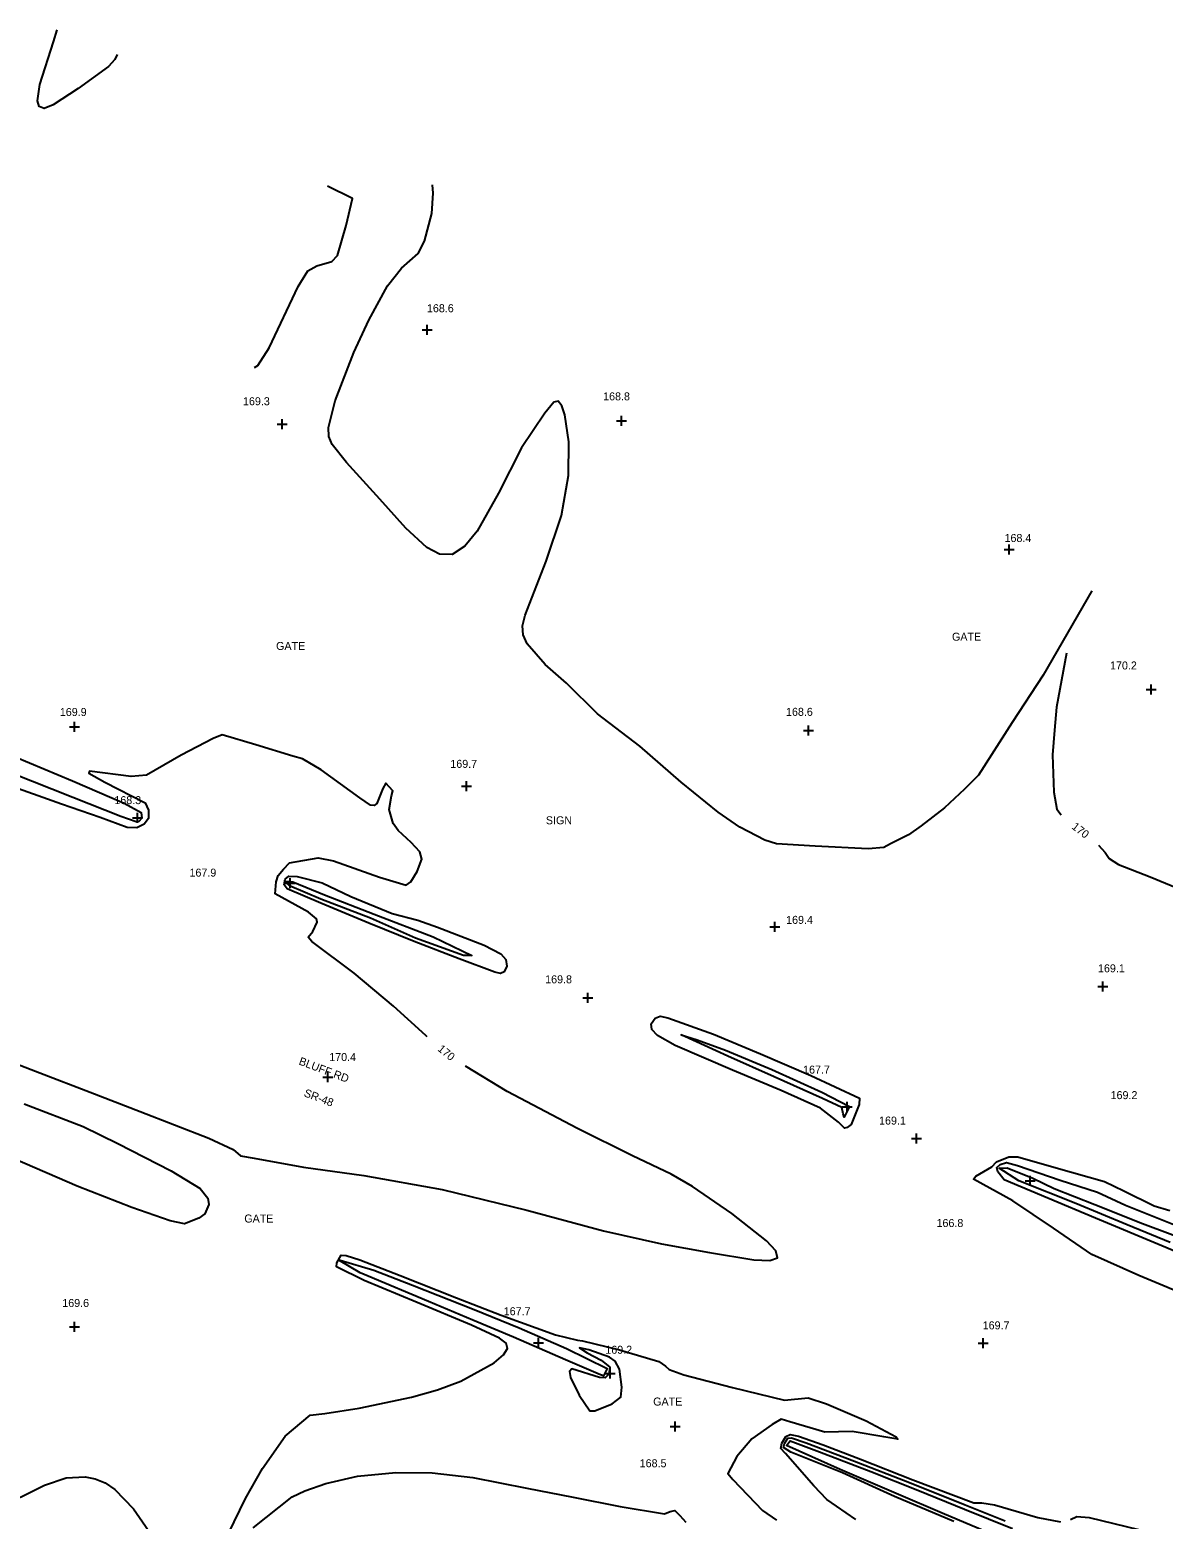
# Model space of a CAD drawing. Extents: x 1475150 to 2003689, y 770235 to 1112803.
# Drawn here: x 1997963.8 to 1998247, y 775726.9 to 776099.2 of the extents above; entities that cross this region are included whole.
import ezdxf

# ---------------------------------------------------------------- set-up
doc = ezdxf.new("R2010")
doc.units = 0
for name, color, linetype in [('RD_DTM_Major1', 7, 'Continuous'), ('RD_DTM_Major1_Lbl', 7, 'Continuous'), ('RD_DTM_Minor1', 7, 'Continuous'), ('RD_DTM_Spot_Elev', 7, 'Continuous'), ('RD_TX_Misc1', 7, 'Continuous')]:
    doc.layers.add(name, color=color, linetype=linetype)

msp = doc.modelspace()

# ---------------------------------------------------------------- linework, layer by layer
at = {"layer": 'RD_DTM_Major1'}
for points in [[(1998019.96, 776014.76), (1998020.76, 776015.27), (1998023.63, 776019.73), (1998030.91, 776035.03), (1998033.26, 776038.93), (1998035.54, 776040.16), (1998039.32, 776041.24), (1998040.67, 776042.8), (1998042.84, 776050.28), (1998044.45, 776057.02), (1998038.17, 776060.1)], [(1998222.83, 775943.4), (1998220.32, 775929.85), (1998219.81, 775924.17), (1998219.34, 775917.98), (1998219.66, 775908.62), (1998220.4, 775904.42), (1998221.54, 775902.99)], [(1998063.14, 775847.46), (1998062.74, 775847.79), (1998054.7, 775855.1), (1998044.9, 775863.38), (1998034.29, 775871.33), (1998033.4, 775872.39), (1998034.52, 775873.83), (1998035.66, 775876.11), (1998035.43, 775876.98), (1998033.43, 775878.65), (1998025.12, 775883.25), (1998025.35, 775886.22), (1998025.85, 775887.77), (1998027.24, 775889.41), (1998028.67, 775890.99), (1998035.87, 775892.18), (1998039.7, 775891.44), (1998051.19, 775887.36), (1998057.85, 775885.35), (1998059.05, 775886.23), (1998060.63, 775888.83), (1998061.75, 775891.91), (1998061.31, 775893.71), (1998059.09, 775896.03), (1998055.87, 775899.08), (1998054.6, 775900.79), (1998053.64, 775904.28), (1998054.23, 775907.75), (1998054.53, 775908.99), (1998052.8, 775910.9), (1998052.02, 775909.54), (1998050.55, 775905.8), (1998049.85, 775905.3), (1998048.97, 775905.4), (1998046.29, 775907.23), (1998036.62, 775914.25), (1998031.93, 775916.97), (1998029.53, 775917.6), (1998020.26, 775920.48), (1998011.87, 775923), (1998009.6, 775922.06), (1998001.63, 775917.86), (1997992.98, 775912.89), (1997989.11, 775912.55), (1997978.73, 775913.89), (1997978.56, 775913.42), (1997982.53, 775911.15), (1997992.66, 775905.98), (1997993.5, 775904.09), (1997993.44, 775902.08), (1997992.4, 775900.62), (1997990.58, 775899.73), (1997988.13, 775899.81), (1997981.41, 775902.27), (1997971.78, 775905.64), (1997957.46, 775910.7)], [(1998230.85, 775895.41), (1998232.49, 775893.59), (1998233.49, 775892.09), (1998235.87, 775890.53), (1998243.76, 775887.44), (1998256.67, 775882.1), (1998274.92, 775874.43), (1998292.72, 775867.08), (1998293.86, 775866.91), (1998296.21, 775871.31)], [(1997955.67, 775842.58), (1997966.34, 775838.47), (1997978.93, 775833.62), (1997991.42, 775828.79), (1998008.55, 775822.13), (1998014.65, 775819.34), (1998016.45, 775817.72), (1998019.84, 775817.12), (1998032.24, 775814.9), (1998047.24, 775812.8), (1998066.85, 775809.3), (1998088, 775804.11), (1998107.12, 775799.01), (1998121.68, 775795.73), (1998133.67, 775793.53), (1998144.73, 775791.74), (1998148.69, 775791.55), (1998150.65, 775792.25), (1998150.18, 775794.02), (1998147.91, 775796.49), (1998139.2, 775803.34), (1998129.4, 775810.1), (1998124.03, 775813.16), (1998114.42, 775817.75), (1998100.7, 775824.58), (1998083.13, 775833.84), (1998072.68, 775840.16)]]:
    msp.add_lwpolyline(points, dxfattribs=at)
at = {"layer": 'RD_DTM_Minor1'}
for points in [[(1997985.62, 776093.01), (1997985.05, 776091.81), (1997983.5, 776090.03), (1997975.89, 776084.54), (1997969.69, 776080.42), (1997967.42, 776079.55), (1997966.17, 776080.01), (1997965.76, 776081.48), (1997966.37, 776085.54), (1997969.75, 776096.22), (1997970.66, 776099.2)], [(1998229.15, 775958.98), (1998217, 775937.88), (1998209.3, 775926.06), (1998200.84, 775912.88), (1998197.36, 775909.38), (1998192.32, 775904.71), (1998186.53, 775900.23), (1998183.35, 775897.98), (1998178.9, 775895.69), (1998177.16, 775894.82), (1998173.31, 775894.44), (1998160.04, 775895.15), (1998150.4, 775895.7), (1998147.44, 775896.6), (1998141.22, 775899.91), (1998135.8, 775903.67), (1998126.54, 775911.16), (1998116.25, 775920.13), (1998105.65, 775928.21), (1998097.93, 775935.87), (1998092.59, 775940.56), (1998088.11, 775945.74), (1998087.08, 775947.98), (1998086.93, 775950.24), (1998087.56, 775952.91), (1998092.85, 775966.37), (1998096.67, 775977.76), (1998098.44, 775987.76), (1998098.46, 775996.17), (1998097.5, 776002.99), (1998096.74, 776005.24), (1998095.81, 776006.34), (1998094.76, 776006.13), (1998092.54, 776003.37), (1998086.71, 775994.69), (1998080.92, 775983.33), (1998075.56, 775973.85), (1998072.55, 775970.14), (1998069.39, 775968.07), (1998066.16, 775968.13), (1998063.03, 775969.76), (1998057.81, 775974.61), (1998051.3, 775981.87), (1998042.95, 775991.07), (1998039.37, 775995.57), (1998038.57, 775997.53), (1998038.45, 775999.76), (1998040.15, 776006.43), (1998044.8, 776018.5), (1998048.51, 776026.62), (1998053.2, 776035.17), (1998056.72, 776039.61), (1998060.88, 776043.29), (1998062.44, 776046.36), (1998064.26, 776053.26), (1998064.6, 776058.36), (1998064.43, 776060.42)], [(1997960.19, 775917.47), (1997974.45, 775911.48), (1997987.39, 775905.86), (1997991.67, 775903.54), (1997991.85, 775902.16), (1997991.08, 775901.34), (1997990.38, 775901.18), (1997986.53, 775902.52), (1997974.57, 775907.33), (1997959.29, 775913.38), (1997946.8, 775918.47), (1997934.61, 775924.25), (1997922.47, 775930.31), (1997917.27, 775932.19), (1997907.92, 775935.34), (1997901.2, 775938.84), (1997901.83, 775938.87), (1997908.61, 775936.91), (1997920.8, 775932.65), (1997932.19, 775928.38), (1997945.99, 775923.09), (1997960.19, 775917.47)], [(1998028.09, 775884.43), (1998027.34, 775885.43), (1998027.59, 775886.87), (1998028.51, 775887.66), (1998030.6, 775887.53), (1998036.91, 775885.98), (1998043.99, 775882.58), (1998054.39, 775878.34), (1998060.74, 775876.65), (1998065.71, 775874.92), (1998077.36, 775870.36), (1998081.51, 775868.22), (1998082.77, 775866.83), (1998083.01, 775865.17), (1998082.35, 775863.73), (1998081.44, 775863.31), (1998080.02, 775863.65), (1998071.11, 775867.01), (1998059.83, 775871.3), (1998048.5, 775875.89), (1998036.52, 775880.91), (1998028.09, 775884.43)], [(1998027.5, 775886.41), (1998029.56, 775886.23), (1998037.48, 775882.98), (1998049.9, 775878.12), (1998064.62, 775872.5), (1998074.3, 775867.84), (1998072.19, 775867.84), (1998060.18, 775872.12), (1998048.91, 775877.13), (1998036.52, 775881.91), (1998028.72, 775885.24), (1998027.5, 775886.41)], [(1998168.06, 775824.81), (1998167.38, 775824.67), (1998165.86, 775826.16), (1998161.36, 775829.62), (1998151.53, 775834.02), (1998139.43, 775839.16), (1998125.04, 775845.3), (1998120.65, 775847.78), (1998119.24, 775849.31), (1998119.11, 775850.74), (1998120.11, 775852.18), (1998121.3, 775852.67), (1998123.26, 775852.23), (1998134.67, 775848.18), (1998146.35, 775843.26), (1998158.99, 775837.83), (1998171.12, 775832.13), (1998171.02, 775830.55), (1998169.01, 775825.57), (1998168.06, 775824.81)], [(1998137.64, 775844.15), (1998149.25, 775839.29), (1998161.71, 775833.65), (1998168.62, 775830.02), (1998167.25, 775827.39), (1998167.04, 775828.26), (1998166.71, 775829.82), (1998161.84, 775832.05), (1998149.81, 775837.49), (1998138.25, 775842.61), (1998126.55, 775848), (1998130.58, 775846.74), (1998137.64, 775844.15)], [(1997962.45, 775830.74), (1997977.16, 775825.03), (1997985.81, 775820.79), (1997999.12, 775813.98), (1998006.39, 775809.59), (1998008.31, 775807.13), (1998008.53, 775805.52), (1998007.55, 775803.26), (1998006.03, 775802.13), (1998002.45, 775800.7), (1997998.93, 775801.47), (1997989.34, 775804.84), (1997975.68, 775810.13), (1997960.05, 775816.86)], [(1998255.51, 775781.71), (1998240.92, 775787.83), (1998229.2, 775793.07), (1998219.56, 775799.62), (1998209.43, 775806.5), (1998199.58, 775811.91), (1998200.22, 775812.62), (1998204.21, 775814.98), (1998205.39, 775816.21), (1998208.46, 775817.49), (1998210.7, 775817.49), (1998220.24, 775814.74), (1998232.36, 775811.31), (1998237.2, 775808.99), (1998244.78, 775805.26), (1998248.67, 775804.08)], [(1998258.73, 775790.17), (1998246.69, 775795.22), (1998230.07, 775802.17), (1998218.2, 775807.17), (1998207.26, 775811.74), (1998205.67, 775813.74), (1998205.45, 775814.83), (1998206.27, 775815.6), (1998207.83, 775816.07), (1998210.61, 775815.35), (1998221.24, 775811.67), (1998230.57, 775808.67), (1998237.56, 775805.39), (1998250.53, 775800.22)], [(1998248.76, 775796.09), (1998237.97, 775800.51), (1998225.17, 775805.79), (1998210.91, 775811.47), (1998205.99, 775814.64), (1998208.04, 775814.75), (1998214.39, 775812.18), (1998219.72, 775809.58), (1998229.93, 775805.6), (1998241.85, 775800.79), (1998255.02, 775795.88)], [(1998012.08, 775720.44), (1998017.73, 775732.04), (1998021.93, 775739.58), (1998027.64, 775747.64), (1998033.86, 775752.93), (1998037.52, 775753.34), (1998046.14, 775754.69), (1998059.17, 775757.36), (1998065.72, 775759.22), (1998071.48, 775761.41), (1998079.84, 775766.02), (1998082.18, 775768.01), (1998083.17, 775769.59), (1998082.81, 775770.9), (1998081.15, 775772.18), (1998074.18, 775775.41), (1998060.59, 775781.06), (1998047.4, 775786.57), (1998040.49, 775789.97), (1998040.56, 775791.02), (1998041.62, 775792.86), (1998042.87, 775792.8), (1998046.28, 775791.74), (1998056.33, 775787.82), (1998070.41, 775782.26), (1998081.56, 775777.87), (1998095.19, 775772.98), (1998100.63, 775771.63), (1998101.92, 775771.51), (1998111.16, 775769.23), (1998120.97, 775766.34), (1998122.67, 775765.13), (1998123.57, 775764.33), (1998127.19, 775763), (1998139.4, 775759.79), (1998152.4, 775756.61), (1998158.31, 775757.21), (1998162.89, 775755.76), (1998172.75, 775751.45), (1998180.26, 775747.49), (1998180.74, 775746.9), (1998177.16, 775747.45), (1998169.28, 775748.78), (1998162.44, 775748.63), (1998153.68, 775751.24), (1998151.59, 775751.86), (1998149.28, 775750.6), (1998144.22, 775746.97), (1998140.5, 775742.58), (1998138.2, 775738.32), (1998139.5, 775736.8), (1998146.89, 775729.1), (1998150.38, 775726.69)], [(1998046.39, 775788.51), (1998041, 775791.67), (1998041.37, 775791.68), (1998049.74, 775789.18), (1998059.48, 775785.37), (1998074.81, 775779.35), (1998086.12, 775774.74), (1998097.94, 775769.57), (1998108.08, 775764.59), (1998107.17, 775762.74), (1998106.4, 775762.96), (1998097.67, 775766.76), (1998084.65, 775772.42), (1998074.48, 775776.66), (1998063.42, 775781.28), (1998048.34, 775787.61), (1998046.39, 775788.51)], [(1998106.54, 775766.64), (1998108.73, 775764.89), (1998108.47, 775763.16), (1998107.56, 775762.26), (1998106.17, 775762.32), (1998099.27, 775764.5), (1998098.63, 775763.85), (1998098.89, 775762.29), (1998101.05, 775757.86), (1998103.71, 775753.98), (1998105.03, 775753.96), (1998109.33, 775755.74), (1998111.49, 775757.42), (1998111.77, 775759.88), (1998111.13, 775764.39), (1998110.04, 775766.41), (1998108.63, 775767.41), (1998103.52, 775769.26), (1998101.18, 775769.71), (1998103.09, 775768.46), (1998106.54, 775766.64)], [(1998170.18, 775726.82), (1998162.98, 775731.83), (1998159.68, 775735.23), (1998152.67, 775743.34), (1998151.43, 775744.6), (1998151.69, 775745.87), (1998152.73, 775747.6), (1998153.76, 775748.1), (1998155.86, 775747.68), (1998162.07, 775745.48), (1998171.36, 775741.87), (1998184.48, 775736.77), (1998199.65, 775730.96), (1998201.67, 775730.96), (1998204.87, 775730.46), (1998215.66, 775727.29), (1998221.34, 775726.25)], [(1998194.71, 775726.28), (1998179.88, 775732.6), (1998166.86, 775738.45), (1998153.99, 775743.64), (1998152.12, 775744.84), (1998152.37, 775745.81), (1998153.23, 775747.19), (1998154.11, 775747.27), (1998157.83, 775746.01), (1998169.86, 775741.42), (1998183.59, 775736.08), (1998197.56, 775730.5), (1998207.52, 775726.47)], [(1998204.58, 775722.97), (1998191.8, 775728.39), (1998180.87, 775733.1), (1998166.28, 775739.33), (1998152.9, 775745.34), (1998153.76, 775746.48), (1998161.11, 775743.7), (1998173.93, 775738.8), (1998185.71, 775734.17), (1998197.36, 775729.41), (1998209.34, 775724.56)], [(1997955.53, 775729.52), (1997967.48, 775735.38), (1997972.87, 775737.26), (1997977.68, 775737.51), (1997980.15, 775737), (1997982.63, 775735.98), (1997985.1, 775734.34), (1997989.74, 775729.46), (1997995.92, 775720.59)], [(1998019.65, 775724.75), (1998029.38, 775732.49), (1998032.5, 775733.98), (1998037.8, 775735.86), (1998045.72, 775737.69), (1998055.26, 775738.53), (1998064.36, 775738.48), (1998074.55, 775737.3), (1998087.97, 775734.69), (1998099.55, 775732.41), (1998111.35, 775730.08), (1998122.4, 775728.27), (1998123.84, 775728.78), (1998125.01, 775729.05), (1998126.21, 775727.86), (1998127.7, 775726.16)], [(1998223.85, 775726.83), (1998225.4, 775727.55), (1998228.52, 775727.33), (1998240.82, 775724.33)]]:
    msp.add_lwpolyline(points, dxfattribs=at)
at = {"layer": 'RD_DTM_Spot_Elev'}
for p, q in [((1998061.89, 776024.19), (1998064.39, 776024.19)), ((1998063.14, 776022.94), (1998063.14, 776025.44)), ((1998025.65, 776000.61), (1998028.15, 776000.61)), ((1998026.9, 775999.36), (1998026.9, 776001.86)), ((1998110.43, 776001.46), (1998112.93, 776001.46)), ((1998111.68, 776000.21), (1998111.68, 776002.71)), ((1998207.25, 775969.25), (1998209.75, 775969.25)), ((1998208.5, 775968), (1998208.5, 775970.5)), ((1998242.76, 775934.31), (1998245.26, 775934.31)), ((1998244.01, 775933.06), (1998244.01, 775935.56)), ((1997975, 775923.75), (1997975, 775926.25)), ((1997973.75, 775925), (1997976.25, 775925)), ((1998157.1, 775924.08), (1998159.6, 775924.08)), ((1998158.35, 775922.83), (1998158.35, 775925.33)), ((1998072.92, 775908.89), (1998072.92, 775911.39)), ((1998071.67, 775910.14), (1998074.17, 775910.14)), ((1997989.46, 775902.22), (1997991.96, 775902.22)), ((1997990.71, 775900.97), (1997990.71, 775903.47)), ((1998027.62, 775885.85), (1998030.12, 775885.85)), ((1998028.87, 775884.6), (1998028.87, 775887.1)), ((1998148.75, 775875), (1998151.25, 775875)), ((1998150, 775873.75), (1998150, 775876.25)), ((1998230.69, 775860.06), (1998233.19, 775860.06)), ((1998231.94, 775858.81), (1998231.94, 775861.31)), ((1998101.96, 775857.23), (1998104.46, 775857.23)), ((1998103.21, 775855.98), (1998103.21, 775858.48)), ((1998037.01, 775837.36), (1998039.51, 775837.36)), ((1998038.26, 775836.11), (1998038.26, 775838.61)), ((1998166.75, 775829.97), (1998169.25, 775829.97)), ((1998168, 775828.72), (1998168, 775831.22)), ((1998184.08, 775822.05), (1998186.58, 775822.05)), ((1998185.33, 775820.8), (1998185.33, 775823.3)), ((1998212.54, 775811.5), (1998215.04, 775811.5)), ((1998213.79, 775810.25), (1998213.79, 775812.75)), ((1997973.75, 775775), (1997976.25, 775775)), ((1997975, 775773.75), (1997975, 775776.25)), ((1998089.64, 775770.96), (1998092.14, 775770.96)), ((1998090.89, 775769.71), (1998090.89, 775772.21)), ((1998200.8, 775770.93), (1998203.3, 775770.93)), ((1998202.05, 775769.68), (1998202.05, 775772.18)), ((1998107.57, 775763.35), (1998110.07, 775763.35)), ((1998108.82, 775762.1), (1998108.82, 775764.6)), ((1998125.05, 775748.8), (1998125.05, 775751.3)), ((1998123.8, 775750.05), (1998126.3, 775750.05))]:
    msp.add_line(p, q, dxfattribs=at)

# ---------------------------------------------------------------- texts
at = {"layer": 'RD_DTM_Major1_Lbl'}
for rotation, p in [(322.3813, (1998223.97, 775899.67)), (320.5181, (1998065.55, 775844.17))]:
    msp.add_text('170', height=2, rotation=rotation, dxfattribs=at).set_placement(p)
at = {"layer": 'RD_DTM_Spot_Elev'}
for s, p in [('168.6', (1998063.05, 776028.6)), ('168.8', (1998107.07, 776006.57)), ('169.3', (1998017.09, 776005.35)), ('168.4', (1998207.36, 775971.17)), ('170.2', (1998233.72, 775939.3)), ('169.9', (1997971.33, 775927.67)), ('168.6', (1998152.76, 775927.71)), ('169.7', (1998068.89, 775914.71)), ('168.3', (1997984.95, 775905.64)), ('167.9', (1998003.72, 775887.52)), ('169.4', (1998152.79, 775875.71)), ('169.8', (1998092.59, 775860.85)), ('169.1', (1998230.71, 775863.6)), ('170.4', (1998038.63, 775841.42)), ('167.7', (1998157.03, 775838.28)), ('169.2', (1998233.86, 775831.9)), ('169.1', (1998176.01, 775825.54)), ('166.8', (1998190.37, 775799.93)), ('169.6', (1997971.94, 775779.94)), ('167.7', (1998082.23, 775777.88)), ('169.7', (1998201.9, 775774.35)), ('169.2', (1998107.62, 775768.25)), ('168.5', (1998116.2, 775739.88))]:
    msp.add_text(s, height=2, dxfattribs=at).set_placement(p)
at = {"layer": 'RD_TX_Misc1'}
for s, p in [('GATE', (1998194.23, 775946.49)), ('GATE', (1998025.36, 775944.18)), ('SIGN', (1998092.76, 775900.6)), ('GATE', (1998017.41, 775801.05)), ('GATE', (1998119.57, 775755.3))]:
    msp.add_text(s, height=2, dxfattribs=at).set_placement(p)
for s, p in [('BLUFF RD', (1998030.87, 775840.62)), ('SR-48', (1998032.15, 775832.67))]:
    msp.add_text(s, height=2, rotation=339.175, dxfattribs=at).set_placement(p)

doc.saveas('drawing.dxf')
